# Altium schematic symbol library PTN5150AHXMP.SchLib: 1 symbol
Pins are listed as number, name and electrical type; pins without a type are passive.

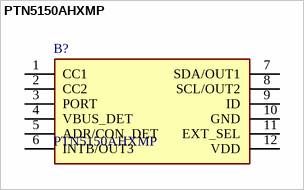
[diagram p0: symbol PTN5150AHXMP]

## PTN5150AHXMP
designator B?
USB Controller USB Interface 12-X2QFN (1.6x1.6), 2.7V ~ 5.5V , 100 uA , -40C ~ 85C; Manufacturer_Name: NXP; Geometry.Height: 0.4mm
footprint PTN5150AHXMP
pins: 1 CC1, 2 CC2, 3 PORT, 4 VBUS_DET, 5 ADR/CON_DET, 6 INTB/OUT3, 7 SDA/OUT1, 8 SCL/OUT2, 9 ID, 10 GND, 11 EXT_SEL, 12 VDD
